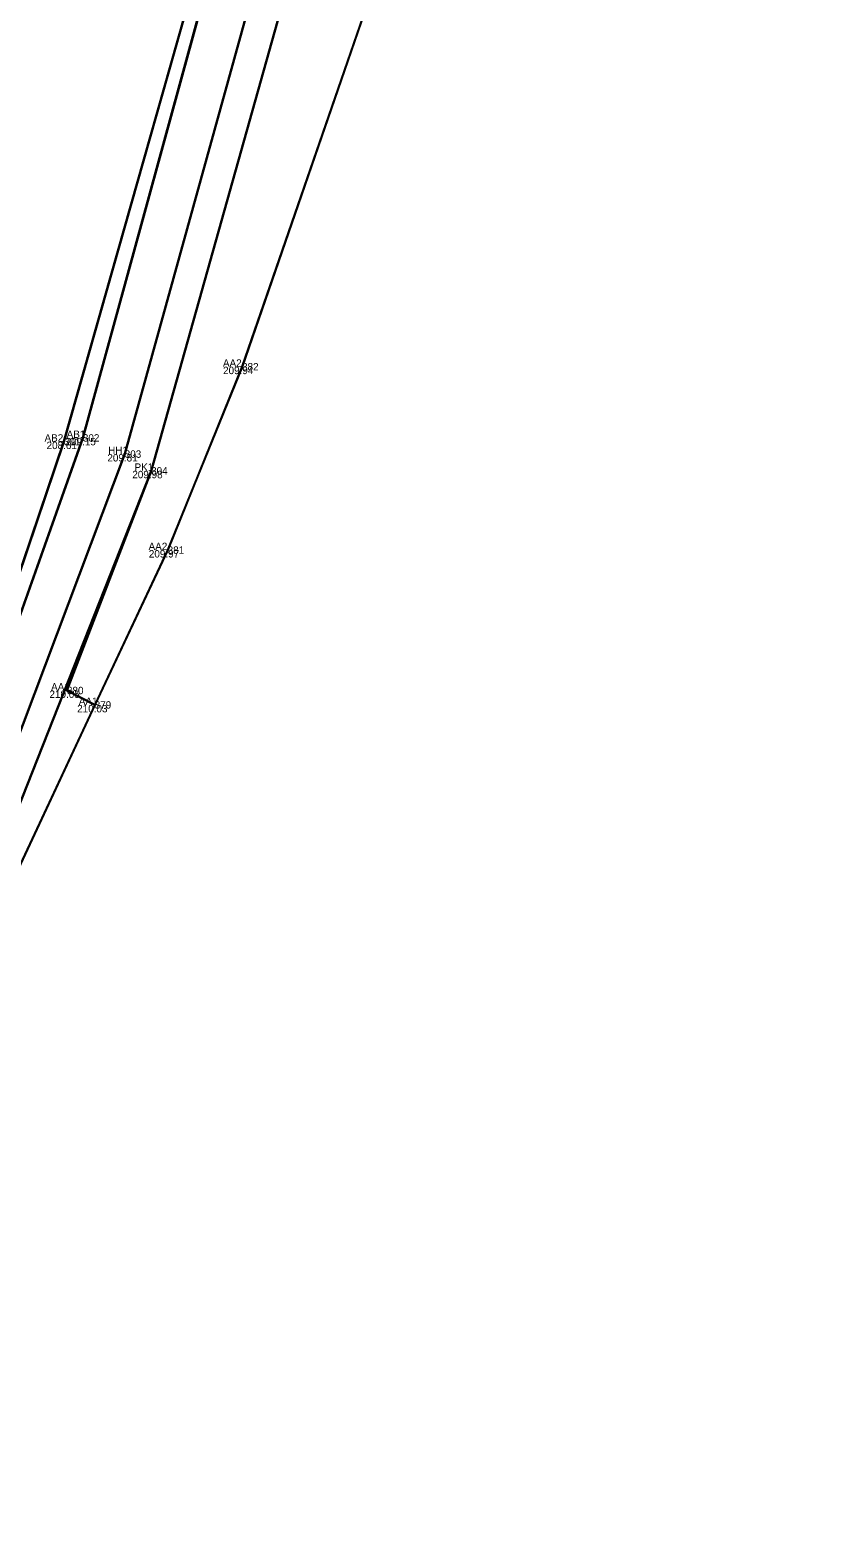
# Model space of a CAD drawing. Extents: x -263091 to -262565, y -1238731 to -1237092.
# Drawn here: x -262837.85 to -262816.76, y -1238112.64 to -1238071.97 of the extents above; entities that cross this region are included whole.
import ezdxf

# ---------------------------------------------------------------- set-up
doc = ezdxf.new("R2010")
doc.units = 0
for name, color, linetype in [('02_Oplotenie', 7, 'Continuous'), ('03_Asfalt', 7, 'Continuous'), ('05_Hrana_terénu', 7, 'Continuous'), ('09_Múrik', 7, 'Continuous'), ('Groma (21)', 7, 'Continuous'), ('Groma (22)', 7, 'Continuous'), ('Groma (23)', 7, 'Continuous'), ('Groma (24)', 7, 'Continuous'), ('U003_Asfalt', 7, 'Continuous'), ('U003_Betónové_múriky', 7, 'Continuous'), ('U003_Betónové_panely', 7, 'Continuous'), ('U003_Zeleň_mimo', 7, 'Continuous'), ('U003_Zeleň_vnútro', 7, 'Continuous'), ('U003_Zeleň_zatrávňovač', 7, 'Continuous'), ('U005_Betóny_prídavné', 7, 'Continuous')]:
    doc.layers.add(name, color=color, linetype=linetype)

msp = doc.modelspace()

# ---------------------------------------------------------------- linework, layer by layer
at = {"layer": '02_Oplotenie'}
msp.add_lwpolyline([(-262819.762, -1237938.034), (-262820.788, -1237960.675), (-262821.837, -1237980.919), (-262823.308, -1238002.106), (-262824.582, -1238026.068), (-262825.82, -1238041.973), (-262827.772, -1238056.552), (-262830.57, -1238069.546), (-262834.589, -1238083.855), (-262839.328, -1238095.835), (-262848.782, -1238120.942), (-262853.684, -1238135.175), (-262859.896, -1238152.781), (-262867.698, -1238174.329), (-262874.833, -1238193.487), (-262881.88, -1238212.036), (-262887.174, -1238225.693), (-262888.829, -1238230.138)], dxfattribs=at)
at = {"layer": '03_Asfalt'}
for points in [[(-262816.76, -1237934.791), (-262817.067, -1237940.584), (-262818.198, -1237960.603), (-262819.351, -1237980.318), (-262820.259, -1237997.242), (-262821.106, -1238014.516), (-262822.726, -1238037.787), (-262824.929, -1238056.475), (-262826.695, -1238065.295), (-262832.135, -1238081.046), (-262834.142, -1238085.994), (-262836.111, -1238090.171)], [(-262836.859, -1238089.782), (-262836.111, -1238090.171), (-262839.692, -1238097.821), (-262843.275, -1238106.507), (-262847.806, -1238119.202), (-262853.613, -1238135.97), (-262859.461, -1238152.467), (-262860.389, -1238156.54), (-262862.798, -1238164.04), (-262866.716, -1238174.359), (-262874.069, -1238193.289), (-262881.205, -1238211.833), (-262885.932, -1238224.211), (-262887.38, -1238228.337), (-262891.202, -1238238.204), (-262891.593, -1238238.614)]]:
    msp.add_lwpolyline(points, dxfattribs=at)
at = {"layer": '05_Hrana_terénu'}
msp.add_lwpolyline([(-262849.564, -1238120.544), (-262839.894, -1238095.583), (-262835.301, -1238083.403), (-262831.402, -1238069.334), (-262828.632, -1238056.516), (-262826.436, -1238041.83), (-262825.08, -1238026.06), (-262823.863, -1238001.967), (-262822.633, -1237980.847), (-262821.298, -1237960.54), (-262820.334, -1237939.047), (-262819.871, -1237937.657)], dxfattribs=at)
at = {"layer": '09_Múrik'}
for points in [[(-262840.924, -1238094.827), (-262836.941, -1238083.068), (-262832.969, -1238069.042), (-262830.214, -1238056.416), (-262828.063, -1238041.942), (-262826.83, -1238026.465), (-262825.494, -1238001.855), (-262824.316, -1237980.84), (-262823.031, -1237960.337), (-262821.719, -1237936.336)], [(-262840.6, -1238094.732), (-262836.43, -1238082.967), (-262832.633, -1238069.1), (-262829.86, -1238056.421), (-262827.688, -1238042.018), (-262826.338, -1238026.448), (-262825.108, -1238001.872), (-262823.89, -1237980.741), (-262822.602, -1237960.47), (-262821.253, -1237936.39)]]:
    msp.add_lwpolyline(points, dxfattribs=at)
at = {"layer": 'Groma (21)'}
for centre in [(-262832.135, -1238081.046), (-262836.941, -1238083.068), (-262836.43, -1238082.967), (-262835.301, -1238083.403), (-262834.589, -1238083.855), (-262834.142, -1238085.994), (-262836.859, -1238089.782), (-262836.111, -1238090.171)]:
    msp.add_circle(centre, 0.01, dxfattribs=at)
at = {"layer": 'U003_Asfalt'}
for points in [[(-262836.86, -1238089.78), (-262834.59, -1238083.86), (-262830.57, -1238069.55), (-262827.77, -1238056.55), (-262825.82, -1238041.97), (-262824.58, -1238026.07), (-262823.31, -1238002.11), (-262821.84, -1237980.92), (-262820.79, -1237960.68), (-262819.76, -1237938.03), (-262819.87, -1237937.66), (-262818.51, -1237937.77), (-262818.3, -1237934.7)], [(-262816.76, -1237934.79), (-262817.07, -1237940.58), (-262818.2, -1237960.6), (-262819.35, -1237980.32), (-262820.26, -1237997.24), (-262821.11, -1238014.52), (-262822.73, -1238037.79), (-262824.93, -1238056.48), (-262826.7, -1238065.3), (-262832.14, -1238081.05), (-262834.14, -1238085.99), (-262836.11, -1238090.17), (-262836.86, -1238089.78)], [(-262821.11, -1238014.52), (-262822.73, -1238037.79), (-262824.93, -1238056.48), (-262826.7, -1238065.3), (-262832.14, -1238081.05), (-262834.14, -1238085.99), (-262836.11, -1238090.17), (-262836.86, -1238089.78), (-262834.59, -1238083.86), (-262830.57, -1238069.55), (-262827.77, -1238056.55), (-262825.82, -1238041.97), (-262824.58, -1238026.07), (-262823.31, -1238002.11)]]:
    msp.add_lwpolyline(points, dxfattribs=at)
at = {"layer": 'U003_Betónové_múriky'}
msp.add_lwpolyline([(-262821.25, -1237936.39), (-262822.6, -1237960.47), (-262823.89, -1237980.74), (-262825.11, -1238001.87), (-262826.34, -1238026.45), (-262827.69, -1238042.02), (-262829.86, -1238056.42), (-262832.63, -1238069.1), (-262836.43, -1238082.97), (-262840.6, -1238094.73), (-262840.92, -1238094.83), (-262836.94, -1238083.07), (-262832.97, -1238069.04), (-262830.21, -1238056.42), (-262828.06, -1238041.94), (-262826.83, -1238026.47), (-262825.49, -1238001.86), (-262824.32, -1237980.84), (-262823.03, -1237960.34), (-262821.72, -1237936.34)], close=True, dxfattribs=at)
msp.add_lwpolyline([(-262821.72, -1237936.34), (-262821.25, -1237936.39), (-262822.6, -1237960.47), (-262823.89, -1237980.74), (-262825.11, -1238001.87), (-262826.34, -1238026.45), (-262827.69, -1238042.02), (-262829.86, -1238056.42), (-262832.63, -1238069.1), (-262836.43, -1238082.97), (-262840.6, -1238094.73), (-262840.92, -1238094.83), (-262836.94, -1238083.07), (-262832.97, -1238069.04), (-262830.21, -1238056.42), (-262828.06, -1238041.94), (-262826.83, -1238026.47), (-262825.49, -1238001.86), (-262824.32, -1237980.84), (-262823.03, -1237960.34), (-262821.72, -1237936.34)], dxfattribs=at)
at = {"layer": 'U003_Betónové_panely'}
msp.add_lwpolyline([(-262822, -1237934.47), (-262822.23, -1237936.28), (-262821.72, -1237936.34), (-262823.03, -1237960.34), (-262824.32, -1237980.84), (-262825.49, -1238001.86), (-262826.83, -1238026.47), (-262828.06, -1238041.94), (-262830.21, -1238056.42), (-262832.97, -1238069.04), (-262836.94, -1238083.07), (-262840.92, -1238094.83), (-262840.6, -1238094.73), (-262841.76, -1238095.81), (-262851.46, -1238119.84), (-262857.2, -1238134.12), (-262863.32, -1238150.73), (-262871.41, -1238173.11), (-262878.16, -1238192.14), (-262884.61, -1238210.94), (-262889.86, -1238225.24), (-262892.75, -1238232.5), (-262895.19, -1238238.55), (-262900.83, -1238252.4)], dxfattribs=at)
msp.add_lwpolyline([(-262822, -1237934.47), (-262822.23, -1237936.28), (-262821.72, -1237936.34), (-262823.03, -1237960.34), (-262824.32, -1237980.84), (-262825.49, -1238001.86), (-262826.83, -1238026.47), (-262828.06, -1238041.94), (-262830.21, -1238056.42), (-262832.97, -1238069.04), (-262836.94, -1238083.07), (-262840.92, -1238094.83), (-262840.6, -1238094.73), (-262841.76, -1238095.81), (-262851.46, -1238119.84), (-262857.2, -1238134.12), (-262863.32, -1238150.73), (-262871.41, -1238173.11), (-262878.16, -1238192.14), (-262884.61, -1238210.94), (-262889.86, -1238225.24), (-262892.75, -1238232.5), (-262895.19, -1238238.55), (-262900.83, -1238252.4)], dxfattribs=at)
at = {"layer": 'U003_Zeleň_mimo'}
msp.add_lwpolyline([(-262848.78, -1238120.94), (-262839.33, -1238095.84), (-262834.59, -1238083.86), (-262836.86, -1238089.78), (-262836.11, -1238090.17), (-262839.69, -1238097.82), (-262843.28, -1238106.51), (-262847.81, -1238119.2)], dxfattribs=at)
at = {"layer": 'U003_Zeleň_vnútro'}
msp.add_lwpolyline([(-262849.56, -1238120.54), (-262839.89, -1238095.58), (-262835.3, -1238083.4), (-262831.4, -1238069.33), (-262828.63, -1238056.52), (-262826.44, -1238041.83), (-262825.08, -1238026.06), (-262823.86, -1238001.97), (-262822.63, -1237980.85), (-262821.3, -1237960.54), (-262820.33, -1237939.05), (-262819.87, -1237937.66), (-262819.76, -1237938.03), (-262820.79, -1237960.68), (-262821.84, -1237980.92), (-262823.31, -1238002.11), (-262824.58, -1238026.07), (-262825.82, -1238041.97), (-262827.77, -1238056.55), (-262830.57, -1238069.55), (-262834.59, -1238083.86), (-262839.33, -1238095.84), (-262848.78, -1238120.94)], dxfattribs=at)
msp.add_lwpolyline([(-262849.56, -1238120.54), (-262839.89, -1238095.58), (-262835.3, -1238083.4), (-262831.4, -1238069.33), (-262828.63, -1238056.52), (-262826.44, -1238041.83), (-262825.08, -1238026.06), (-262823.86, -1238001.97), (-262822.63, -1237980.85), (-262821.3, -1237960.54), (-262820.33, -1237939.05), (-262819.87, -1237937.66), (-262819.76, -1237938.03), (-262820.79, -1237960.68), (-262821.84, -1237980.92), (-262823.31, -1238002.11), (-262824.58, -1238026.07), (-262825.82, -1238041.97), (-262827.77, -1238056.55), (-262830.57, -1238069.55), (-262834.59, -1238083.86), (-262839.33, -1238095.84), (-262848.78, -1238120.94)], dxfattribs=at)
at = {"layer": 'U003_Zeleň_zatrávňovač'}
for points in [[(-262851.46, -1238119.84), (-262841.76, -1238095.81), (-262840.6, -1238094.73), (-262836.43, -1238082.97), (-262832.63, -1238069.1), (-262829.86, -1238056.42), (-262827.69, -1238042.02), (-262826.34, -1238026.45), (-262825.11, -1238001.87)], [(-262823.86, -1238001.97), (-262825.08, -1238026.06), (-262826.44, -1238041.83), (-262828.63, -1238056.52), (-262831.4, -1238069.33), (-262835.3, -1238083.4), (-262839.89, -1238095.58), (-262849.56, -1238120.54)]]:
    msp.add_lwpolyline(points, dxfattribs=at)
at = {"layer": 'U005_Betóny_prídavné'}
for points in [[(-262851.46, -1238119.84), (-262841.76, -1238095.81), (-262840.6, -1238094.73), (-262836.43, -1238082.97), (-262832.63, -1238069.1), (-262829.86, -1238056.42), (-262827.69, -1238042.02), (-262826.34, -1238026.45), (-262825.11, -1238001.87)], [(-262823.86, -1238001.97), (-262825.08, -1238026.06), (-262826.44, -1238041.83), (-262828.63, -1238056.52), (-262831.4, -1238069.33), (-262835.3, -1238083.4), (-262839.89, -1238095.58), (-262849.56, -1238120.54)]]:
    msp.add_lwpolyline(points, dxfattribs=at)

# ---------------------------------------------------------------- texts
at = {"layer": 'Groma (22)'}
for s, p in [('382', (-262832.135, -1238081.146)), ('301', (-262836.941, -1238083.168)), ('302', (-262836.43, -1238083.067)), ('303', (-262835.301, -1238083.503)), ('304', (-262834.589, -1238083.955)), ('381', (-262834.142, -1238086.094)), ('380', (-262836.859, -1238089.882)), ('379', (-262836.111, -1238090.271))]:
    msp.add_text(s, height=0.2, dxfattribs=at).set_placement(p)
at = {"layer": 'Groma (23)'}
for s, p in [('209.94', (-262832.647, -1238081.246)), ('208.61', (-262837.409, -1238083.268)), ('209.15', (-262836.898, -1238083.167)), ('209.81', (-262835.769, -1238083.603)), ('209.98', (-262835.096, -1238084.055)), ('209.97', (-262834.65, -1238086.194)), ('210.05', (-262837.331, -1238089.982)), ('210.03', (-262836.583, -1238090.371))]:
    msp.add_text(s, height=0.2, dxfattribs=at).set_placement(p)
at = {"layer": 'Groma (24)'}
for s, p in [('AA2', (-262832.65, -1238081.046)), ('AB2', (-262837.465, -1238083.068)), ('AB1', (-262836.868, -1238082.967)), ('HH1', (-262835.748, -1238083.403)), ('PK1', (-262835.036, -1238083.855)), ('AA2', (-262834.657, -1238085.994)), ('AA1', (-262837.287, -1238089.782)), ('AA1', (-262836.539, -1238090.171))]:
    msp.add_text(s, height=0.2, dxfattribs=at).set_placement(p)

doc.saveas('drawing.dxf')
